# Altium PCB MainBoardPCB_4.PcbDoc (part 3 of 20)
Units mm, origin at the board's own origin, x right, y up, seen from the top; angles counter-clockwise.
Board outline 333.63 x 349.38 mm, 16 copper layers (L1, L2 (GND), L3 (Sign), L4 (GND), L5 (Sign), L6 (PWR/GND), L7(PWR/GND), L8 (Plane_GND), L9 (PWR/GND), L10 (PWR/GND), L11 (PWR/GND), L12 (Sign), L13 (GND), L14 (Sign), L15 (GND), L16), stack 2.502 mm thick; 2205 components, 1648 nets, 8314 pads, 3172 vias.
Unrouted connection lines stored in the file: 5141.
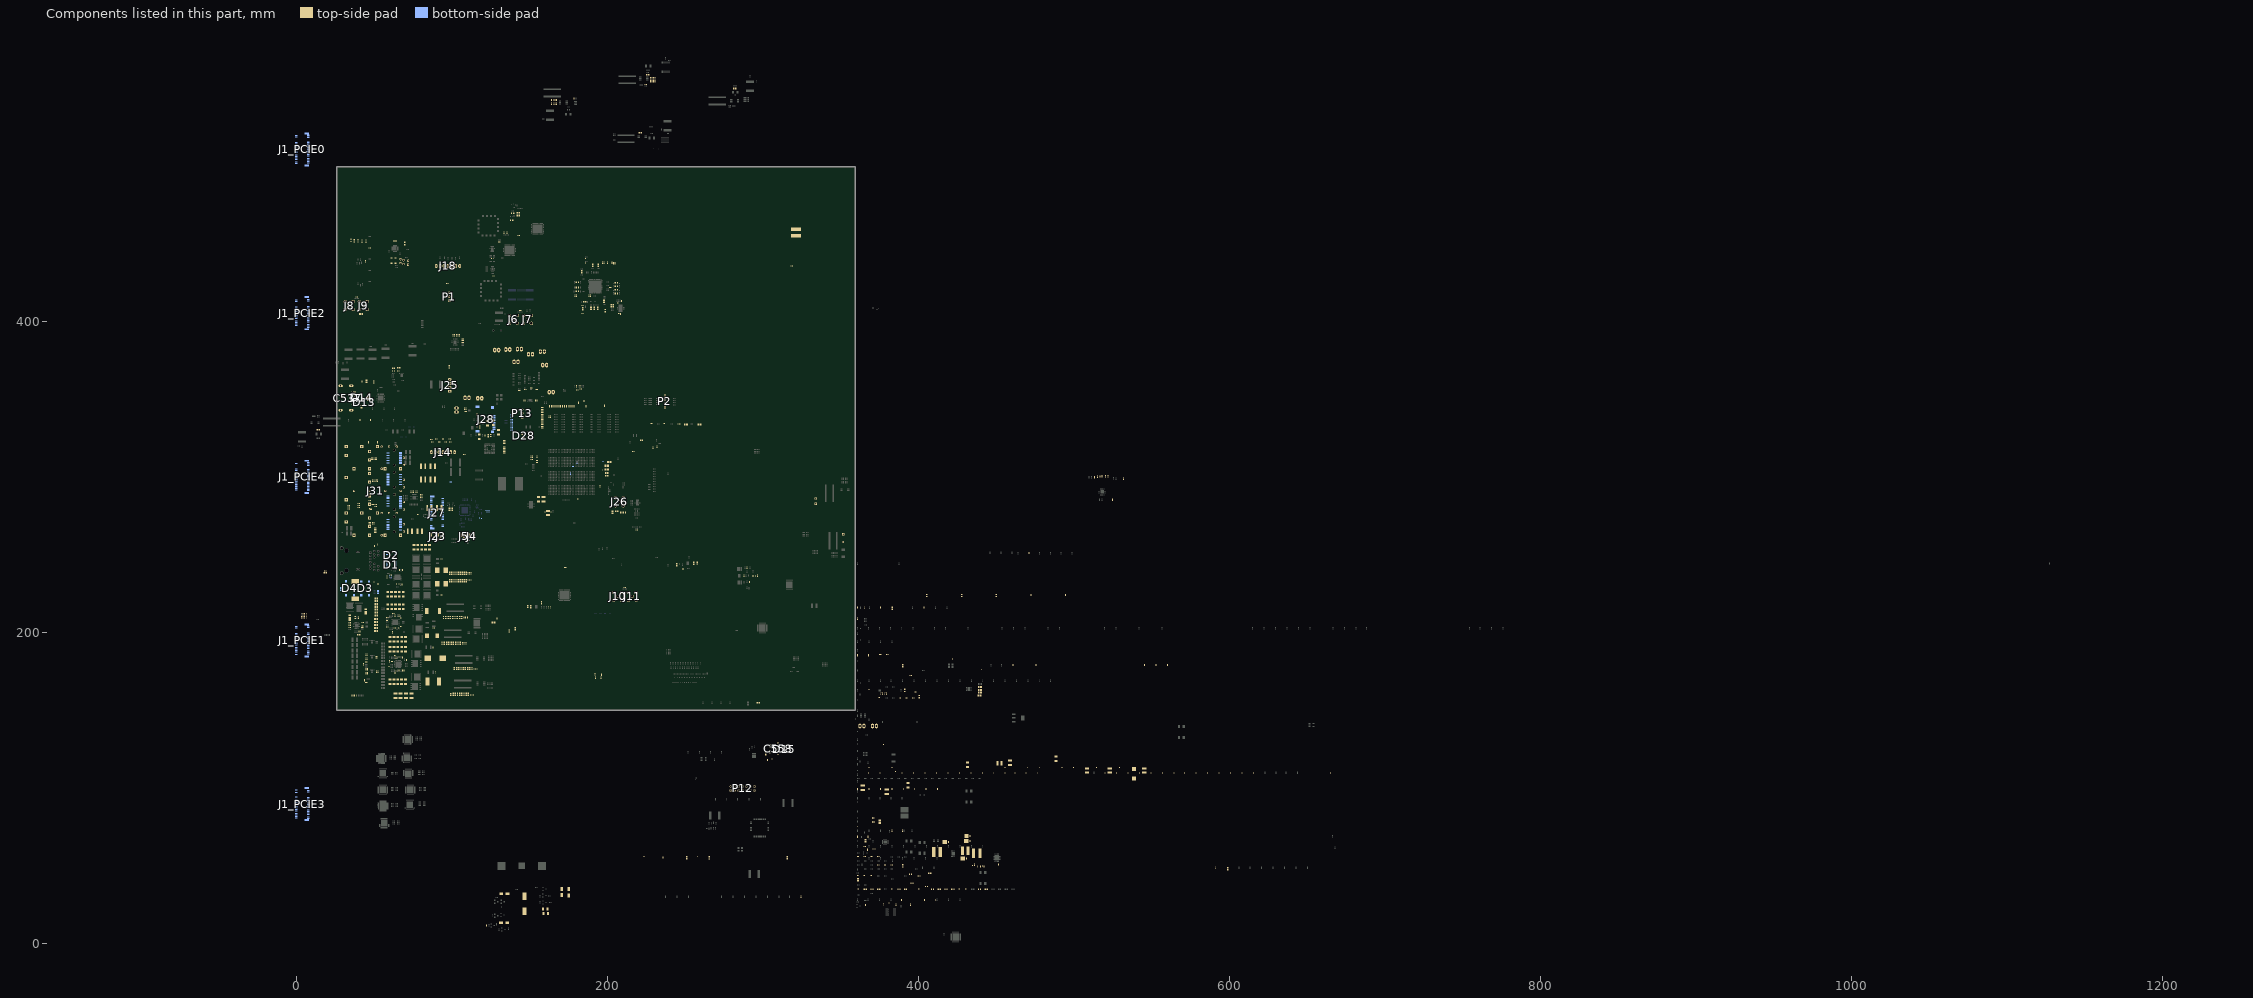
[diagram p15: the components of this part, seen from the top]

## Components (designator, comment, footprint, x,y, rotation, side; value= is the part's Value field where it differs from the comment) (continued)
C333 "10nF" "CAP 0201/0603 RF" 125.971,429.449 r270 top
C334 "100nF" "CAP 0402/1005 RF" 133.51,457.002 r270 top
C335 "100nF" "CAP 0402/1005 RF" 135.6,457.002 r270 top
C336 "100nF" "CAP 0402/1005 RF" 209.427,277.13 r90 top
C337 "100nF" "CAP 0402/1005 RF" 210.486,277.13 r90 top
C338 "100nF" "CAP 0402/1005 RF" 211.544,277.13 r90 top
C339 "10uF" "CAP 0805/2012 RF" 203.289,277.201 r90 top
C340 "1uF" "CAP 0402/1005 RF" 208.369,277.13 r90 top
C341 "100nF" "CAP 0402/1005 RF" 213.821,283.997 r0 top
C342 "100nF" "CAP 0402/1005 RF" 126.635,439.984 r90 top
C343 "100nF" "CAP 0402/1005 RF" 125.635,439.984 r90 top
C344 "10nF" "CAP 0201/0603 RF" 127.056,429.449 r270 top
C345 "22pF" "CAP 0402/1005 RF" 66.32,240.08 r270 top
C346 "100nF" "CAP 0402/1005 RF" 68.336,240.08 r90 top
C347 "10uF" "CAP 1206/3216" 78.111,254.825 r270 top
C348 "10uF" "CAP 1206/3216" 75.629,254.825 r270 top
C349 "22pF" "CAP 0402/1005 RF" 66.055,230.697 r90 top
C350 "100nF" "CAP 0402/1005 RF" 68.072,230.712 r270 top
C351 "1uF" "CAP 0402/1005 RF" 60.756,236.764 r0 top
C352 "10uF" "CAP 1206/3216" 62.772,195.58 r90 top
C353 "10uF" "CAP 1206/3216" 60.29,195.58 r90 top
C354 "4.7 µF" "CAP 0603/1608 RF" 439.306,34.836 r0 top
C355 "4.7 µF" "CAP 0603/1608 RF" 443.624,34.836 r0 top
C356 "1uF" "CAP 0402/1005 RF" 60.541,233.839 r0 top
C357 "100nF" "CAP 0402/1005 RF" 64.44,230.697 r90 top
C358 "1uF" "CAP 0603/1608 RF" 58.293,235.623 r270 top
C359 "100nF" "CAP 0402/1005 RF" 112.323,233.238 r270 top
C360 "470nF" "CAP 0402/1005 RF" 112.324,237.989 r90 top
C361 "1uF" "CAP 0402/1005 RF" 110.434,233.237 r270 top
C362 "4.7uF" "CAP 0603/1608 RF" 101.381,237.989 r90 top
C363 "10uF" "CAP 0603/1608 RF" 100.061,237.989 r90 top
C364 "22uF" "CAP 0603/1608 RF" 102.7,237.989 r90 top
C365 "10uF" "CAP 0603/1608 RF" 98.742,233.237 r270 top
C366 "22uF" "CAP 0603/1608 RF" 98.742,237.989 r90 top
C367 "10uF" "CAP 0603/1608 RF" 101.381,233.237 r270 top
C368 "22uF" "CAP 0603/1608 RF" 100.061,233.237 r270 top
C369 "10uF" "CAP 0603/1608 RF" 102.7,233.237 r270 top
C370 "22uF" "CAP 0603/1608 RF" 104.02,237.989 r90 top
C371 "10uF" "CAP 1206/3216 - 0.8MM" 67.736,195.58 r90 top
C372 "10uF" "CAP 1206/3216 - 0.8MM" 80.593,254.825 r270 top
C373 "10uF" "CAP 1206/3216 - 0.8MM" 85.557,254.825 r270 top
C374 "10uF" "CAP 1206/3216 - 0.8MM" 65.254,195.58 r90 top
C375 "10uF" "CAP 1206/3216 - 0.8MM" 83.075,254.825 r270 top
C376 "10uF" "CAP 1206/3216 - 0.8MM" 70.218,195.58 r90 top
C377 "100nF" "CAP 0402/1005 RF" 111.364,233.238 r270 top
C378 "470nF" "CAP 0402/1005 RF" 110.435,237.989 r90 top
C379 "1uF" "CAP 0402/1005 RF" 111.365,237.989 r90 top
C380 "4.7uF" "CAP 0603/1608 RF" 105.339,237.989 r90 top
C381 "10uF" "CAP 0603/1608 RF" 105.339,233.237 r270 top
C382 "22uF" "CAP 0603/1608 RF" 106.659,233.237 r270 top
C383 "10uF" "CAP 0603/1608 RF" 109.298,237.989 r90 top
C384 "22uF" "CAP 0603/1608 RF" 107.978,233.238 r270 top
C385 "10uF" "CAP 0603/1608 RF" 104.02,233.237 r270 top
C386 "22uF" "CAP 0603/1608 RF" 106.659,237.989 r90 top
C387 "10uF" "CAP 0603/1608 RF" 109.297,233.238 r270 top
C388 "22uF" "CAP 0603/1608 RF" 107.978,237.989 r90 top
C389 "22pF" "CAP 0402/1005 RF" 68.211,183.823 r270 top
C390 "100nF" "CAP 0402/1005 RF" 70.891,182.214 r90 top
C391 "10uF" "CAP 1206/3216" 61.258,224.638 r270 top
C392 "10uF" "CAP 1206/3216" 58.776,224.638 r90 top
C393 "22pF" "CAP 0402/1005 RF" 68.185,175.427 r90 top
C394 "100nF" "CAP 0402/1005 RF" 69.151,175.427 r270 top
C395 "1uF" "CAP 0402/1005 RF" 59.93,181.401 r270 top
C396 "10uF" "CAP 1206/3216" 61.334,216.433 r270 top
C397 "10uF" "CAP 1206/3216" 58.852,216.433 r90 top
C398 "1uF" "CAP 0402/1005 RF" 61.458,181.317 r0 top
C399 "100nF" "CAP 0402/1005 RF" 59.524,178.467 r90 top
C400 "10uF" "CAP 1206/3216 - 0.8MM" 68.78,216.433 r270 top
C401 "10uF" "CAP 1206/3216 - 0.8MM" 66.298,216.433 r270 top
C402 "10uF" "CAP 1206/3216 - 0.8MM" 63.816,216.433 r270 top
C403 "10uF" "CAP 1206/3216 - 0.8MM" 68.704,224.607 r90 top
C404 "10uF" "CAP 1206/3216 - 0.8MM" 66.222,224.637 r90 top
C405 "10uF" "CAP 1206/3216 - 0.8MM" 63.74,224.637 r90 top
C406 "100nF" "CAP 0402/1005 RF" 116.15,176.851 r90 top
C407 "470nF" "CAP 0402/1005 RF" 115.176,176.847 r90 top
C408 "1uF" "CAP 0402/1005 RF" 114.205,176.851 r90 top
C409 "4.7uF" "CAP 0603/1608 RF" 110.122,176.847 r90 top
C410 "10uF" "CAP 0603/1608 RF" 108.699,176.847 r90 top
C411 "22uF" "CAP 0603/1608 RF" 112.941,176.847 r90 top
C412 "10uF" "CAP 0603/1608 RF" 111.544,176.847 r90 top
C413 "22uF" "CAP 0603/1608 RF" 107.302,176.847 r90 top
C414 "10uF" "CAP 0603/1608 RF" 103.061,176.847 r90 top
C415 "22uF" "CAP 0603/1608 RF" 101.638,176.847 r90 top
C416 "10uF" "CAP 0603/1608 RF" 105.905,176.847 r90 top
C417 "22uF" "CAP 0603/1608 RF" 104.47,176.851 r90 top
C418 "100nF" "CAP 0402/1005 RF" 113.877,160.146 r90 top
C419 "470nF" "CAP 0402/1005 RF" 112.903,160.146 r90 top
C420 "1uF" "CAP 0402/1005 RF" 111.932,160.146 r90 top
C421 "4.7uF" "CAP 0603/1608 RF" 107.849,160.146 r90 top
C422 "10uF" "CAP 0603/1608 RF" 106.426,160.146 r90 top
C423 "22uF" "CAP 0603/1608 RF" 110.668,160.146 r90 top
C424 "10uF" "CAP 0603/1608 RF" 109.271,160.146 r90 top
C425 "22uF" "CAP 0603/1608 RF" 105.029,160.147 r90 top
C426 "10uF" "CAP 0603/1608 RF" 100.787,160.147 r90 top
C427 "22uF" "CAP 0603/1608 RF" 99.37,160.137 r90 top
C428 "10uF" "CAP 0603/1608 RF" 103.632,160.147 r90 top
C429 "22uF" "CAP 0603/1608 RF" 102.197,160.147 r90 top
C430 "22pF" "CAP 0402/1005 RF" 65.978,210.639 r270 top
C431 "100nF" "CAP 0402/1005 RF" 67.391,209.114 r0 top
C432 "10uF" "CAP 1206/3216" 62.758,168.173 r270 top
C433 "10uF" "CAP 1206/3216" 60.276,168.173 r90 top
C434 "22pF" "CAP 0402/1005 RF" 65.578,202.374 r90 top
C435 "100nF" "CAP 0402/1005 RF" 67.406,203.864 r0 top
C436 "1uF" "CAP 0402/1005 RF" 58.356,207.523 r0 top
C437 "10uF" "CAP 1206/3216" 62.772,189.281 r270 top
C438 "10uF" "CAP 1206/3216" 60.29,189.281 r90 top
C439 "1uF" "CAP 0402/1005 RF" 58.455,209.529 r0 top
C440 "100nF" "CAP 0402/1005 RF" 58.449,203.522 r0 top
C441 "10uF" "CAP 1206/3216 - 0.8MM" 70.218,189.281 r270 top
C442 "10uF" "CAP 1206/3216 - 0.8MM" 67.736,189.281 r270 top
C443 "10uF" "CAP 1206/3216 - 0.8MM" 65.254,189.281 r270 top
C444 "10uF" "CAP 1206/3216 - 0.8MM" 70.204,168.173 r90 top
C445 "10uF" "CAP 1206/3216 - 0.8MM" 67.722,168.173 r90 top
C446 "10uF" "CAP 1206/3216 - 0.8MM" 65.24,168.173 r90 top
C447 "100nF" "CAP 0402/1005 RF" 109.987,209.5 r90 top
C448 "470nF" "CAP 0402/1005 RF" 108.87,209.5 r90 top
C449 "1uF" "CAP 0402/1005 RF" 107.777,209.5 r90 top
C450 "4.7uF" "CAP 0603/1608 RF" 106.482,209.5 r90 top
C451 "10uF" "CAP 0603/1608 RF" 104.983,209.5 r90 top
C452 "22uF" "CAP 0603/1608 RF" 103.51,209.499 r90 top
C453 "10uF" "CAP 0603/1608 RF" 102.037,209.499 r90 top
C454 "22uF" "CAP 0603/1608 RF" 100.564,209.499 r90 top
C455 "10uF" "CAP 0603/1608 RF" 99.091,209.499 r90 top
C456 "22uF" "CAP 0603/1608 RF" 97.617,209.499 r90 top
C457 "10uF" "CAP 0603/1608 RF" 96.144,209.498 r90 top
C458 "22uF" "CAP 0603/1608 RF" 94.671,209.498 r90 top
C459 "100nF" "CAP 0402/1005 RF" 108.979,192.987 r90 top
C460 "470nF" "CAP 0402/1005 RF" 107.861,192.987 r90 top
C461 "1uF" "CAP 0402/1005 RF" 106.769,192.987 r90 top
C462 "4.7uF" "CAP 0603/1608 RF" 105.474,192.987 r90 top
C463 "10uF" "CAP 0603/1608 RF" 103.975,192.986 r90 top
C464 "22uF" "CAP 0603/1608 RF" 102.502,192.971 r90 top
C465 "10uF" "CAP 0603/1608 RF" 101.028,192.986 r90 top
C466 "22uF" "CAP 0603/1608 RF" 99.555,192.986 r90 top
C467 "10uF" "CAP 0603/1608 RF" 98.082,192.986 r90 top
C468 "22uF" "CAP 0603/1608 RF" 96.609,192.986 r90 top
C469 "10uF" "CAP 0603/1608 RF" 95.136,192.986 r90 top
C470 "22uF" "CAP 0603/1608 RF" 93.662,192.986 r90 top
C471 "100nF" "CAP 0402/1005 RF" 52.457,231.085 r90 top
C472 "100nF" "CAP 0402/1005 RF" 50.082,231.991 r90 top
C473 "100nF" "CAP 0402/1005 RF" 52.387,256.453 r270 top
C474 "100nF" "CAP 0402/1005 RF" 50.178,255.53 r270 top
C479 "100nF" "CAP 0402/1005 RF" 124.389,277.877 r90 bottom
C480 "27pF" "CAP 0402/1005 RF" 117.665,273.146 r90 bottom
C481 "27pF" "CAP 0402/1005 RF" 119.05,273.654 r90 bottom
C482 "100nF" "CAP 0402/1005 RF" 123.424,277.852 r90 bottom
C483 "100nF" "CAP 0402/1005 RF" 122.509,277.903 r90 bottom
C484 "100nF" "CAP 0402/1005 RF" 121.468,277.941 r90 bottom
C485 "1uF" "CAP 0402/1005 RF" 520.141,109.982 r90 top
C486 "1uF" "CAP 0402/1005 RF" 527.507,109.982 r90 top
C487 "100nF" "CAP 0402/1005 RF" 534.873,109.982 r90 top
C488 "100nF" "CAP 0402/1005 RF" 542.252,109.982 r90 top
C489 "10uF" "CAP 0402/1005 RF" 549.618,109.982 r90 top
C490 "10nF" "CAP 0402/1005 RF" 556.984,109.982 r90 top
C491 "1uF" "CAP 0402/1005 RF" 564.35,109.982 r90 top
C492 "1uF" "CAP 0402/1005 RF" 571.208,109.982 r90 top
C493 "1uF" "CAP 0402/1005 RF" 578.587,109.982 r90 top
C494 "100nF" "CAP 0402/1005 RF" 585.953,109.982 r90 top
C495 "100nF" "CAP 0402/1005 RF" 593.319,109.982 r90 top
C496 "100nF" "CAP 0402/1005 RF" 600.685,109.982 r90 top
C497 "10uF" "CAP 0402/1005 RF" 608.051,109.982 r90 top
C498 "10nF" "CAP 0402/1005 RF" 615.429,109.982 r90 top
C499 "1uF" "CAP 0402/1005 RF" 367.944,109.982 r90 top
C500 "1uF" "CAP 0402/1005 RF" 375.31,109.982 r90 top
C501 "100nF" "CAP 0402/1005 RF" 385.255,110.105 r90 top
C502 "100nF" "CAP 0402/1005 RF" 389.547,109.982 r90 top
C503 "10uF" "CAP 0402/1005 RF" 396.913,109.982 r90 top
C504 "10nF" "CAP 0402/1005 RF" 404.279,109.982 r90 top
C505 "1uF" "CAP 0402/1005 RF" 411.645,109.982 r90 top
C506 "1uF" "CAP 0402/1005 RF" 419.011,109.982 r90 top
C507 "1uF" "CAP 0402/1005 RF" 426.39,109.982 r90 top
C508 "1uF" "CAP 0402/1005 RF" 433.756,109.982 r90 top
C509 "100nF" "CAP 0402/1005 RF" 441.122,109.982 r90 top
C510 "100nF" "CAP 0402/1005 RF" 448.488,109.982 r90 top
C511 "100nF" "CAP 0402/1005 RF" 455.6,109.982 r90 top
C512 "100nF" "CAP 0402/1005 RF" 462.216,109.982 r90 top
C513 "10uF" "CAP 0402/1005 RF" 469.328,109.982 r90 top
C514 "10nF" "CAP 0402/1005 RF" 476.44,109.982 r90 top
C515 "4.7uF" "CAP 0603/1608 RF" 136.804,200.812 r90 top
C516 "4.7uF" "CAP 0603/1608 RF" 140.83,202.298 r90 top
C517 "100nF" "CAP 0402/1005 RF" 118.173,334.607 r90 top
C518 "2.2uF" "CAP 1206/3216 - 0.8MM" 126.632,334.937 r90 top
C519 "100nF" "CAP 0402/1005 RF" 121.45,326.621 r90 top
C520 "2.2uF" "CAP 1206/3216 - 0.8MM" 117.602,325.734 r90 top
C521 "100nF" "CAP 0402/1005 RF" 382.93,72.453 r90 top
C522 "1uF" "CAP 0402/1005 RF" 389.788,72.453 r90 top
C523 "4.7uF" "CAP 0603/1608 RF" 117.907,332.121 r90 top
C524 "4.7uF" "CAP 0603/1608 RF" 125.057,326.649 r90 top
C525 "10nF" "CAP 0402/1005 RF" 151.355,313.343 r180 top
C526 "10nF" "CAP 0402/1005 RF" 151.355,312.332 r180 top
C527 "10nF" "CAP 0402/1005 RF" 154.793,309.319 r180 top
C528 "10nF" "CAP 0402/1005 RF" 154.793,310.413 r180 top
C529 "10nF" "CAP 0402/1005 RF" 154.775,312.953 r270 top
C530 "10nF" "CAP 0402/1005 RF" 151.355,311.189 r180 top
C531 "100nF" "CAP 0402/1005 RF" 47.206,447.065 r180 top
C532 "100nF" "CAP 0402/1005 RF" 63.97,451.688 r90 top
C533 "100nF" "CAP 0402/1005 RF" 62.87,451.688 r90 top
C534 "100nF" "CAP 0402/1005 RF" 44.47,438.625 r270 top
C535 "22pF" "CAP 0402/1005 RF" 148.213,330.314 r180 top
C536 "22pF" "CAP 0402/1005 RF" 149.933,330.314 r0 top
C537 "WE-Communication Connectors 692121130100" 692121130100 35.291,358.548 r90 bottom
C538 "1uF" "CAP 0402/1005 RF" 42.177,361.364 r90 top
C539 "4.7uF" "CAP 0603/1608 RF" 49.721,361.034 r90 top
C540 "100nF" "CAP 0402/1005 RF" 45.996,351.904 r180 top
C541 "100nF" "CAP 0402/1005 RF" 46.025,351.079 r180 top
C542 "100nF" "CAP 0402/1005 RF" 46.063,350.101 r180 top
C543 "100nF" "CAP 0402/1005 RF" 46.038,348.996 r180 top
C544 "1uF" "CAP 0402/1005 RF" 403.504,215.989 r90 top
C545 "100nF" "CAP 0402/1005 RF" 360.832,215.989 r90 top
C546 "100nF" "CAP 0402/1005 RF" 365.185,215.849 r90 top
C547 "100nF" "CAP 0402/1005 RF" 375.564,215.989 r90 top
C548 "11pF" "CAP 0402/1005 RF" 62.953,210.639 r270 top
C549 "220pF" "CAP 0402/1005 RF" 62.338,212.229 r180 top
C550 "4.7uF" "CAP 0402/1005 RF" 293.721,236.179 r90 top
C551 "10uF" "CAP 0402/1005 RF" 289.911,241.571 r90 top
C552 "4.7uF" "CAP 0402/1005 RF" 295.118,236.306 r90 top
C553 "10uF" "CAP 0402/1005 RF" 291.435,232.418 r90 top
C554 "4.7uF" "CAP 0402/1005 RF" 296.515,236.433 r90 top
C555 "10uF" "CAP 0402/1005 RF" 287.879,236.366 r90 top
C558 "WR-Communication Connectors 614105150721" 614105150721 309.546,125.025 r90 top
C559 "1uF" "CAP 0402/1005 RF" 301.295,125.371 r90 top
C560 "4.7uF" "CAP 0603/1608 RF" 301.93,121.945 r90 top
C561 "100nF" "CAP 0402/1005 RF" 78.331,275.773 r0 top
C562 "100nF" "CAP 0402/1005 RF" 395.088,172.212 r0 top
C563_5V_to_3V3_for_FTDI "4.7uF" "CAP 0603/1608 RF" 405.447,223.749 r90 top (schematic designator C563)
C563_U_5V_to_3V31 "4.7uF" "CAP 0603/1608 RF" 148.838,216.538 r90 top (schematic designator C563)
C563_U_5V_to_3V32 "4.7uF" "CAP 0603/1608 RF" 255.552,244.424 r270 top (schematic designator C563)
C563_U_5V_to_3V33 "4.7uF" "CAP 0603/1608 RF" 62.446,368.071 r0 top (schematic designator C563)
C564_5V_to_3V3_for_FTDI "4.7uF" "CAP 0603/1608 RF" 427.799,223.749 r90 top (schematic designator C564)
C564_U_5V_to_3V31 "4.7uF" "CAP 0603/1608 RF" 150.832,216.448 r90 top (schematic designator C564)
C564_U_5V_to_3V32 "4.7uF" "CAP 0603/1608 RF" 257.937,244.526 r270 top (schematic designator C564)
C564_U_5V_to_3V33 "4.7uF" "CAP 0603/1608 RF" 65.875,370.103 r0 top (schematic designator C564)
C565_5V_to_3V3_for_FTDI "4.7uF" "CAP 0603/1608 RF" 450.139,223.749 r90 top (schematic designator C565)
C565_U_5V_to_3V31 "4.7uF" "CAP 0603/1608 RF" 157.664,219.018 r270 top (schematic designator C565)
C565_U_5V_to_3V32 "4.7uF" "CAP 0603/1608 RF" 244.615,243.489 r270 top (schematic designator C565)
C565_U_5V_to_3V33 "4.7uF" "CAP 0603/1608 RF" 62.423,369.722 r0 top (schematic designator C565)
C566_5V_to_3V3_for_FTDI "100nF" "CAP 0402/1005 RF" 472.313,224.079 r90 top (schematic designator C566)
C566_U_5V_to_3V31 "100nF" "CAP 0402/1005 RF" 163.601,216.148 r90 top (schematic designator C566)
C566_U_5V_to_3V32 "100nF" "CAP 0402/1005 RF" 246.545,243.522 r270 top (schematic designator C566)
C566_U_5V_to_3V33 "100nF" "CAP 0402/1005 RF" 65.568,368.071 r0 top (schematic designator C566)
C567_5V_to_3V3_for_FTDI "2.2uF" "CAP 0402/1005 RF" 494.665,224.079 r90 top (schematic designator C567)
C567_U_5V_to_3V31 "2.2uF" "CAP 0402/1005 RF" 162.312,216.16 r90 top (schematic designator C567)
C567_U_5V_to_3V32 "2.2uF" "CAP 0402/1005 RF" 248.588,240.767 r90 top (schematic designator C567)
C567_U_5V_to_3V33 "2.2uF" "CAP 0402/1005 RF" 68.018,358.927 r0 top (schematic designator C567)
C568 "4.7uF" "CAP 0402/1005 RF" 392.43,157.861 r0 top
C569 "4.7uF" "CAP 0402/1005 RF" 396.748,157.861 r0 top
C570 "4.7uF" "CAP 0402/1005 RF" 388.112,157.861 r0 top
C571 "1nF" "CAP 0201/0603 RF" 374.777,158.115 r0 top
C572 "10uF" "CAP 0603/1608 RF" 202.4,410.04 r270 top
C573 "10nF" "CAP 0201/0603 RF" 207.236,405.087 r180 top
C574 "10uF" "CAP 0805/2012 RF" 126.822,206.235 r0 top
C575 "10uF" "CAP 0805/2012 RF" 41.641,404.621 r0 top
C576 "10uF" "CAP 0603/1608 RF" 203.797,410.071 r270 top
C577 "10nF" "CAP 0201/0603 RF" 206.789,411.818 r180 top
C578 "100nF" "CAP 0402/1005 RF" 208.996,413.088 r270 top
C579 "100nF" "CAP 0402/1005 RF" 208.496,404.697 r90 top
C580 "4.7uF" "CAP 0805/2012 RF" 439.547,161.275 r0 top
C581 "10uF" "CAP 0805/2012 RF" 439.547,163.068 r0 top
C582 "4.7uF" "CAP 0805/2012 RF" 439.547,164.846 r0 top
C583 "100nF" "CAP 0402/1005 RF" 398.154,161.671 r0 top
C584 "4.7uF" "CAP 0805/2012 RF" 439.293,159.385 r0 top
C585 "100nF" "CAP 0402/1005 RF" 368.198,162.865 r90 top
C586 "2.2uF" "CAP 1206/3216 - 0.8MM" 122.999,334.34 r90 top
C587 "2.2uF" "CAP 1206/3216 - 0.8MM" 130.035,328.79 r90 top
C588 "100nF" "CAP 0402/1005 RF" 185.89,439.977 r270 top
C589 "100nF" "CAP 0402/1005 RF" 185.89,437.114 r270 top
C590 "100nF" "CAP 0402/1005 RF" 184.121,410.218 r0 top
C591 "10uF" "CAP 0402/1005 RF" 184.121,406.154 r0 top
C592 "100nF" "CAP 0402/1005 RF" 184.121,405.069 r0 top
C593 "100nF" "CAP 0402/1005 RF" 188.176,416.431 r90 top
C594 "100nF" "CAP 0402/1005 RF" 189.1,416.431 r90 top
C595 "10uF" "CAP 0805/2012 RF" 28.639,227.851 r90 bottom
C596 "10uF" "CAP 0805/2012 RF" 52.54,225.895 r90 bottom
C597 "1uF" "CAP 0402/1005 RF" 34.332,206.35 r0 top
C598 "10uF" "CAP 0603/1608 RF" 37.846,209.537 r270 top
C603 "43pF" "CAP 0201/0603 RF" 430.339,35.014 r0 top
C604 "1µF" "CAP 0402/1005 RF" 426.022,35.014 r0 top
C605 "100pF" "CAP 0201/0603 RF" 400.126,35.014 r0 top
C606 "4.7 µF" "CAP 0603/1608 RF" 405.267,36.589 r0 top
C607 "4.7 µF" "CAP 0603/1608 RF" 409.092,34.836 r0 top
C609 "FC0H224ZFTBR24" FC0H224ZFTBR24 146.837,25.502 r270 top
C610 "4.7 µF" "CAP 0603/1608 RF" 413.41,34.836 r0 top
C611 "4.7 µF" "CAP 0603/1608 RF" 417.728,34.836 r0 top
C612 "43pF" "CAP 0201/0603 RF" 382.854,35.014 r0 top
C613 "4.7 µF" "CAP 0603/1608 RF" 387.502,34.836 r0 top
C614 "4.7 µF" "CAP 0603/1608 RF" 391.82,34.836 r0 top
C615 "4.7 µF" "CAP 0603/1608 RF" 395.938,38.697 r0 top
C616 "100pF" "CAP 0201/0603 RF" 361.251,35.014 r0 top
C617 "4.7 µF" "CAP 0603/1608 RF" 365.9,34.836 r0 top
C618 "4.7 µF" "CAP 0603/1608 RF" 370.218,34.836 r0 top
C619 "4.7 µF" "CAP 0603/1608 RF" 374.536,34.836 r0 top
C620 "4.7 µF" "CAP 0603/1608 RF" 394.945,44.374 r0 top
C621 "4.7 µF" "CAP 0603/1608 RF" 400.494,43.307 r0 top
C622 "4.7 µF" "CAP 0603/1608 RF" 407.276,45.174 r0 top
C623 "100nF" "CAP 0402/1005 RF" 387.198,43.485 r0 top
C624 "10nF" "CAP 0201/0603 RF" 360.934,43.637 r0 top
C625 "10nF" "CAP 0201/0603 RF" 365.252,43.637 r0 top
C626 "10nF" "CAP 0201/0603 RF" 369.57,43.637 r0 top
C627 "100nF" "CAP 0201/0603 RF" 197.272,309.647 r90 bottom
C628 "470nF" "CAP 0402/1005 RF" 180.397,309.042 r90 bottom
C629 "100nF" "CAP 0201/0603 RF" 197.104,304.165 r90 top
C630 "470nF" "CAP 0402/1005 RF" 176.39,302.031 r90 bottom
C631 "10uF" "CAP 0603/1608 RF" 199.567,300.723 r180 top
C632 "470nF" "CAP 0402/1005 RF" 177.902,306.54 r0 bottom
C633 "3nF" "CAP 0402/1005 RF" 93.442,247.284 r180 top
C634 "330pF" "CAP 0402/1005 RF" 61.028,236.114 r270 bottom
C635 "6.8nF" "CAP 0402/1005 RF" 60.062,236.114 r270 bottom
C636 "3nF" "CAP 0402/1005 RF" 93.332,224.031 r180 top
C637 "1.2nF" "CAP 0402/1005 RF" 87.909,190.2 r270 top
C638 "1.2nF" "CAP 0402/1005 RF" 89.332,174.38 r270 top
C639 "47nF" "CAP 0402/1005 RF" 66.141,183.759 r270 top
C640 "47nF" "CAP 0402/1005 RF" 66.161,175.503 r90 top
C641 "470pF" "CAP 0402/1005 RF" 64.175,175.557 r90 top
C642 "56pF" "CAP 0402/1005 RF" 64.175,183.66 r270 top
C643 "8.2nF" "CAP 0402/1005 RF" 63.51,173.949 r180 top
C644 "820pF" "CAP 0402/1005 RF" 63.565,185.176 r180 top
C645 "1.2nF" "CAP 0402/1005 RF" 88.354,202.857 r180 top
C646 "1.2nF" "CAP 0402/1005 RF" 84.112,207.488 r0 top
C647 "47nF" "CAP 0402/1005 RF" 63.953,210.654 r270 top
C648 "47nF" "CAP 0402/1005 RF" 63.741,202.373 r90 top
C649 "100nF" "CAP 0402/1005 RF" 410.883,27.889 r90 top
C650 "180pF" "CAP 0402/1005 RF" 62.828,202.374 r90 top
C651 "100nF" "CAP 0402/1005 RF" 404.025,27.889 r90 top
C652 "2.2nF" "CAP 0402/1005 RF" 61.925,200.059 r90 top
C653 "100nF" "CAP 0402/1005 RF" 395.059,24.816 r90 top
C654 "100nF" "CAP 0402/1005 RF" 374.205,55.74 r0 top
C655 "5.6nF" "CAP 0402/1005 RF" 369.887,55.74 r0 top
C656 "5.6nF" "CAP 0402/1005 RF" 365.57,55.74 r0 top
C657 "5.6nF" "CAP 0402/1005 RF" 361.251,55.74 r0 top
C658 "100nF" "CAP 0402/1005 RF" 324.574,29.985 r90 top
C659 "4.7uF" "CAP 0603/1608 RF" 315.62,55.118 r90 top
C660 "100nF" "CAP 0402/1005 RF" 591.261,48.603 r90 top
C661 "4.7uF" "CAP 0603/1608 RF" 251.142,55.118 r90 top
C662 "100nF" "CAP 0402/1005 RF" 257.823,55.448 r90 top
C663 "27pF" "CAP 0402/1005 RF" 235.852,55.258 r90 top
C664 "27pF" "CAP 0402/1005 RF" 223.609,55.448 r90 top
C665 "100nF" "CAP 0402/1005 RF" 305.854,118.135 r90 top
C666 "100nF" "CAP 0402/1005 RF" 434.81,50.47 r90 top
C667 "100nF" "CAP 0402/1005 RF" 436.08,50.568 r90 top
C668 "100nF" "CAP 0402/1005 RF" 438.175,49.441 r90 top
C669 "100nF" "CAP 0402/1005 RF" 439.839,49.39 r90 top
C670 "100nF" "CAP 0402/1005 RF" 441.164,49.336 r90 top
C671 "100nF" "CAP 0402/1005 RF" 442.239,49.39 r90 top
C673 "100nF" "CAP 0402/1005 RF" 302.959,117.983 r90 top
C674 "4.7uF" "CAP 0402/1005 RF" 378.549,50.521 r0 top
C675 "4.7uF" "CAP 0402/1005 RF" 382.867,50.521 r0 top
C676 "4.7uF" "CAP 0402/1005 RF" 374.231,50.521 r0 top
C677 "100nF" "CAP 0402/1005 RF" 389.293,27.889 r90 top
C678 "100uF" "CAP 1206/3216" 160.249,19.164 r0 top
C679 "100uF" "CAP 1206/3216" 160.172,22.123 r0 top
C680 "1uF" "CAP 0402/1005 RF" 122.364,11.557 r90 top
C693 "470nF" "CAP 0402/1005 RF" 39.98,209.427 r90 top
C694 "4.7uF" "CAP 0603/1608 RF" 18.637,238.218 r0 top
C695 "10uF" "CAP 0805/2012 RF" 51.294,206.694 r180 top
C696 "10uF" "CAP 0805/2012 RF" 51.294,202.914 r180 top
C697 "10uF" "CAP 0805/2012 RF" 51.294,204.804 r180 top
C698 "10uF" "CAP 0805/2012 RF" 51.294,208.585 r180 top
C699 "10uF" "CAP 0805/2012 RF" 51.294,201.023 r180 top
C700 "1uF" "CAP 0402/1005 RF" 18.637,239.357 r0 top
C701 "12nF" "CAP 0402/1005 RF" 41.097,200.511 r90 top
C702 "36pF" "CAP 0402/1005 RF" 40.17,200.511 r90 top
C703 "15nF" "CAP 0402/1005 RF" 42.517,204.097 r180 top
C704 "1uF" "CAP 0603/1608 RF" 40.157,198.45 r180 top
C705 "10uF" "CAP 0603/1608 RF" 222.045,323.494 r0 top
C706 "10nF" "CAP 0201/0603 RF" 180.892,285.703 r0 top
C707 "10uF" "CAP 0805/2012 RF" 259.183,333.794 r0 top
C708 "10uF" "CAP 0805/2012 RF" 250.534,333.794 r0 top
C709 "10uF" "CAP 0603/1608 RF" 245.988,333.997 r0 top
C710 "10nF" "CAP 0201/0603 RF" 236.679,334.327 r0 top
C711 "100nF" "CAP 0402/1005 RF" 216.682,316.433 r0 top
C712 "100nF" "CAP 0402/1005 RF" 228.36,334.175 r0 top
C713 "100nF" "CAP 0402/1005 RF" 365.57,62.319 r0 top
C714 "330nF" "CAP 0603/1608 RF" 371.479,60.719 r0 top
C715 "100nF" "CAP 0402/1005 RF" 385.712,24.794 r90 top
C716 "100nF" "CAP 0402/1005 RF" 381.013,25.552 r90 top
C717 "100nF" "CAP 0402/1005 RF" 377.762,25.155 r90 top
C718 "100nF" "CAP 0402/1005 RF" 366.065,24.667 r90 top
C719 "1nF" "CAP 0201/0603 RF" 360.68,75.425 r90 top
C720 "1uF" "CAP 0402/1005 RF" 146.52,349.06 r90 top
C721 "1uF" "CAP 0402/1005 RF" 147.511,349.06 r90 top
C722 "1uF" "CAP 0402/1005 RF" 153.683,349.142 r90 top
C723 "1uF" "CAP 0402/1005 RF" 154.673,349.142 r90 top
C724 "10nF" "CAP 0201/0603 RF" 388.645,29.985 r90 top
C725 "10nF" "CAP 0201/0603 RF" 381.279,29.985 r90 top
C726 "10nF" "CAP 0201/0603 RF" 373.901,29.985 r90 top
C727 "10nF" "CAP 0201/0603 RF" 366.535,29.985 r90 top
C728 "100nF" "CAP 0402/1005 RF" 545.478,179.032 r90 top
C729 "100nF" "CAP 0402/1005 RF" 552.844,179.032 r90 top
C730 "100nF" "CAP 0402/1005 RF" 560.21,179.032 r90 top
C731 "2.2uF" "CAP 0402/1005 RF" 40.97,336.575 r90 top
C732 "100nF" "CAP 0402/1005 RF" 47.828,336.575 r90 top
C733 "1uF" "CAP 0402/1005 RF" 129.003,208.851 r90 top
C734 "1uF" "CAP 0402/1005 RF" 475.615,179.032 r90 top
C735 "100nF" "CAP 0402/1005 RF" 460.87,179.032 r90 top
C736 "9pF" "CAP 0201/0603 RF" 421.932,183.172 r90 top
C737 "9pF" "CAP 0201/0603 RF" 440.741,176.352 r90 top
C738 "6TPE680MI" "CAP POL 2917/7343" 538.734,109.042 r90 top
C739 "100uF" "CAP 1210/3225 - 1MM" 545.224,111.176 r90 top
C740 "4.7uF" "CAP 0402/1005 RF" 377.609,128.283 r90 top
C741 "4.7uF" "CAP 0402/1005 RF" 159.918,277.794 r90 top
C742 "100uF" "CAP 1210/3225 - 1MM" 523.113,111.176 r90 top
C743 "4.7uF" "CAP 0402/1005 RF" 529.311,112.674 r90 top
C744 "47uF" "CAP 1206/3216 - 0.8MM" 488.455,118.732 r90 top
C745 "4.7uF" "CAP 0402/1005 RF" 492.455,112.674 r90 top
C746 "4.7uF" "CAP 0402/1005 RF" 499.821,112.674 r90 top
C747 "100uF" "CAP 1210/3225 - 1MM" 508.368,111.176 r90 top
C748 "4.7uF" "CAP 0402/1005 RF" 514.566,112.674 r90 top
C749 "47uF" "CAP 1206/3216 - 0.8MM" 155.753,285.612 r270 top
C750 "4.7uF" "CAP 0402/1005 RF" 231.951,319.325 r90 top
C751 "100uF" "CAP 1210/3225 - 1MM" 452.183,115.875 r0 top
C752 "4.7uF" "CAP 0402/1005 RF" 455.612,112.674 r90 top
C753 "100uF" "CAP 1210/3225 - 1MM" 458.902,116.116 r90 top
C754 "4.7uF" "CAP 0402/1005 RF" 470.357,112.674 r90 top
C755 "4.7uF" "CAP 0402/1005 RF" 477.723,112.674 r90 top
C756 "47uF" "CAP 1206/3216 - 0.8MM" 431.546,114.821 r90 top
C757 "100uF" "CAP 1210/3225 - 1MM" 158.966,285.56 r90 top
C758 "4.7uF" "CAP 0402/1005 RF" 229.361,318.746 r90 top
C759 "47uF" "CAP 1206/3216 - 0.8MM" 393.268,101.803 r90 top
C760 "100uF" "CAP 1210/3225 - 1MM" 161.874,276.784 r270 top
C761 "4.7uF" "CAP 0402/1005 RF" 163.792,277.794 r90 top
C762 "100uF" "CAP 1210/3225 - 1MM" 364.236,99.971 r90 top
C763 "4.7uF" "CAP 0402/1005 RF" 368.211,112.674 r90 top
C764 "100uF" "CAP 1210/3225 - 1MM" 379.705,97.399 r90 top
C765 "4.7uF" "CAP 0402/1005 RF" 382.943,112.674 r90 top
C766 "22uF" "CAP 1210/3225 - 1MM" 73.992,159.249 r270 top
C767 "22uF" "CAP 1210/3225 - 1MM" 70.524,159.25 r270 top
C768 "22uF" "CAP 1210/3225 - 1MM" 67.084,159.249 r270 top
C769 "22uF" "CAP 1210/3225 - 1MM" 63.68,159.249 r270 top
C770 "100nF" "CAP 0402/1005 RF" 38.538,159.341 r270 top
C771 "100nF" "CAP 0402/1005 RF" 37.531,159.341 r270 top
C772 "100nF" "CAP 0402/1005 RF" 36.624,159.341 r270 top
C773 "100nF" "CAP 0402/1005 RF" 35.693,159.341 r270 top
C774 "10uF" "CAP 0805/2012 RF" 51.366,221.852 r0 top
C775 "10uF" "CAP 0805/2012 RF" 51.366,220.038 r0 top
C776 "10uF" "CAP 0805/2012 RF" 51.366,218.215 r0 top
C777 "10uF" "CAP 0805/2012 RF" 51.366,216.47 r0 top
C778 "4.7uF" "CAP 0805/2012 RF" 51.366,214.657 r0 top
C779 "4.7uF" "CAP 0805/2012 RF" 51.366,212.847 r0 top
C780 "4.7uF" "CAP 0805/2012 RF" 51.366,210.952 r0 top
C781 "4.7uF" "CAP 0805/2012 RF" 361.201,40.919 r90 top
C782 "4.7uF" "CAP 0402/1005 RF" 405.041,99.314 r90 top
C783 "100nF" "CAP 0402/1005 RF" 412.407,99.314 r90 top
C784 "4.7uF" "CAP 0402/1005 RF" 390.309,99.314 r90 top
C785 "100nF" "CAP 0402/1005 RF" 397.675,99.314 r90 top
C786 "4.7uF" "CAP 0402/1005 RF" 375.564,99.314 r90 top
C787 "100nF" "CAP 0402/1005 RF" 382.93,99.314 r90 top
C788 "4.7uF" "CAP 0402/1005 RF" 360.832,99.314 r90 top
C789 "100nF" "CAP 0402/1005 RF" 368.198,99.314 r90 top
C790 "100nF" "CAP 0402/1005 RF" 664.972,109.982 r90 top
C791 "100nF" "CAP 0402/1005 RF" 471.068,251.092 r90 top
C792 "100nF" "CAP 0402/1005 RF" 451.536,50.66 r90 top
D1 "SLVU2.8-4BTG TVS Array" SLVU2.8-4 61.176,243.357 r0 bottom
D2 "SLVU2.8-4BTG TVS Array" SLVU2.8-4 61.189,249.58 r0 bottom
D3 "DF01S2" "DF005S2 - DF10S2" 44.298,228.282 r90 bottom locked
D4 "DF01S2" "DF005S2 - DF10S2" 34.43,228.346 r90 bottom locked
D5 "LTST-C190GKT" "LED 0603/1608 GREEN" 37.231,451.764 r90 top
D6 "LTST-C190GKT" "LED 0603/1608 GREEN" 35.199,452.018 r90 top
D7 "LTST-C190GKT" "LED 0603/1608 GREEN" 39.629,451.764 r90 top
D8 "LTST-C190GKT" "LED 0603/1608 GREEN" 44.724,451.637 r90 top
D9 "LTST-C190GKT" "LED 0603/1608 GREEN" 42.311,451.637 r270 top
D10 "LTST-C190GKT" "LED 0603/1608 GREEN" 69.708,450.037 r270 top
D11 "BAT54T1G" BAT54T1G 63.745,439.095 r90 top
D12 "BAT54T1G" BAT54T1G 61.326,439.095 r90 top
D13 "TPD2EUSB30DRTR" TPD2EUSB30 43.739,347.942 r0 top
D14 "TPD4EUSB30DQAR" TPD4EUSB30 42.137,350.757 r180 top
D15 "TPD2EUSB30DRTR" TPD2EUSB30 313.817,124.828 r0 top
D16 "MBRM140T3" "CASE 457" 432.475,65.773 r0 top
D17 "MBRM140T3" "CASE 457" 432.576,68.961 r0 top
D18 "MBRM140T3" "CASE 457" 418.594,65.316 r0 top
D19 "MBRM140T3" "CASE 457" 430.212,54.508 r0 top
D20 "S1M-13-F" S1M-13-F 133.794,31.991 r180 top
D21 "S1M-13-F" S1M-13-F 133.629,13.259 r180 top
D22 "S1M-13-F" S1M-13-F 170.726,33.033 r270 top
D23 "S1M-13-F" S1M-13-F 175.222,32.88 r270 top
D26 "DFLS1100-7" DFLS1100 34.353,210.071 r270 top
D27 "DFLS1100-7" DFLS1100 44.666,214.084 r270 top
D28 "BAS40-04-TP" BAS40-04-TP 146.24,326.314 r270 top
FB1_PCIE0 "Ferrite Chip" "FER 0603/1608" 98.387,370.651 r90 top (schematic designator FB1)
FB1_PCIE1 "Ferrite Chip" "FER 0603/1608" 225.984,558.682 r180 top (schematic designator FB1)
FB1_PCIE2 "Ferrite Chip" "FER 0603/1608" 14.17,330.298 r0 top (schematic designator FB1)
FB1_PCIE3 "Ferrite Chip" "FER 0603/1608" 281.991,549.732 r180 top (schematic designator FB1)
FB1_PCIE4 "Ferrite Chip" "FER 0603/1608" 221.158,521.208 r180 top (schematic designator FB1)
FB2 "220Ohm" "FER 0603/1608" 98.514,279.109 r90 top
FB3 "220Ohm" "FER 0603/1608" 142.701,468.051 r180 top
FB4 "220Ohm" "FER 0603/1608" 100.292,279.109 r90 top
FB5 "220Ohm" "FER 0603/1608" 139.058,469.448 r180 top
FB6 "220Ohm" "FER 0603/1608" 138.383,465.003 r180 top
FB7 "220Ohm" "FER 0603/1608" 142.701,469.702 r180 top
FB8 "220R" "FER 0603/1608" 185.4,412.473 r0 top
FB9 "220R" "FER 0603/1608" 205.829,424.941 r180 top
FB10 "220R" "FER 0603/1608" 197.837,412.845 r90 top
FB11 "220R" "FER 0603/1608" 180.792,425.16 r0 top
FB12 "220R" "FER 0603/1608" 193.764,408.476 r90 top
FB13 "220R" "FER 0603/1608" 183.477,431.815 r270 top
FB14 "220R" "FER 0603/1608" 189.49,408.476 r90 top
FB15 "220R" "FER 0603/1608" 194.272,436.075 r270 top
FB16 "220R" "FER 0603/1608" 205.829,420.266 r180 top
FB17 "220R" "FER 0603/1608" 190.49,436.075 r270 top
FB18 "220R" "FER 0603/1608" 205.829,422.613 r180 top
FB19 "220R" "FER 0603/1608" 205.829,417.914 r180 top
FB20 "220R" "FER 0603/1608" 180.77,421.766 r0 top
FB21 "220R" "FER 0603/1608" 191.49,408.476 r90 top
FB22 "220R" "FER 0603/1608" 180.77,419.266 r0 top
FB23 "Ferrite Chip" "FER 0603/1608" 297.015,154.838 r0 top
FB24 "Ferrite Chip" "FER 0603/1608" 205.996,277.901 r0 top
FB25 "Ferrite Chip" "FER 0603/1608" 123.533,326.369 r90 top
FB26 "220R" "FER 0603/1608" 45.11,361.44 r90 top
FB27 "220R" "FER 0603/1608" 41.93,345.237 r90 top
FB28 "220R" "FER 0603/1608" 390.042,178.498 r90 top
FB29 "220R" "FER 0603/1608" 383.184,215.456 r90 top
FB31 "220R" "FER 0603/1608" 304.432,123.266 r90 top
FB32 "220R" "FER 0603/1608" 304.775,127.089 r90 top
FB33 "120R" "FER 0603/1608" 400.685,158.75 r90 top
FB34 "330R" "FER 0603/1608" 391.325,162.672 r90 top
FB35 "220Ohm" "FER 0603/1608" 366.022,65.915 r90 top
FB36 "220R" "FER 0603/1608" 198.617,406.919 r270 top
FB37 "220R" "FER 0603/1608" 184.121,408.186 r270 top
FB38 "600R" "FER 0805/2012" 201.358,309.448 r180 top
FB39 "600R" "FER 0805/2012" 199.568,307.149 r180 top
FB40 "600R" "FER 0805/2012" 199.579,304.749 r180 top
FB41 "600R" "FER 0805/2012" 375.12,78.105 r90 top
FB42 "120R" "FER 0603/1608" 199.593,302.489 r180 top
FB43 "220R" "FER 0603/1608" 598.881,48.069 r90 top
FB44 "220R" "FER 0603/1608" 265.443,54.915 r90 top
FB45 "120R" "FER 0603/1608" 389.903,49.784 r90 top
J1_PCIE0 "Key M" "M.2 KEY M" 3.725,510.508 r90 bottom (schematic designator J1)
J1_PCIE1 "Key M" "M.2 KEY M" 3.725,194.813 r90 bottom (schematic designator J1)
J1_PCIE2 "Key M" "M.2 KEY M" 3.725,405.276 r90 bottom (schematic designator J1)
J1_PCIE3 "Key M" "M.2 KEY M" 3.725,89.581 r90 bottom (schematic designator J1)
J1_PCIE4 "Key M" "M.2 KEY M" 3.725,300.045 r90 bottom (schematic designator J1)
J2 "1909763-1" TECO-1909763-1_V 88.279,262.674 r0 top
J3 "1909763-1" TECO-1909763-1_V 92.854,262.674 r0 top
J4 "1909763-1" TECO-1909763-1_V 112.869,262.534 r0 top
J5 "1909763-1" TECO-1909763-1_V 107.815,262.534 r0 top
J6 "5-1814832-1" TECO-5-1814832-1_V 139.56,401.249 r180 bottom
J7 "5-1814832-1" TECO-5-1814832-1_V 148.577,401.249 r180 bottom
J8 "5-1814832-1" TECO-5-1814832-1_V 34.011,410.185 r180 bottom
J9 "5-1814832-1" TECO-5-1814832-1_V 43.028,410.185 r180 bottom
J10 "5-1814832-1" TECO-5-1814832-1_V 206.667,223.152 r180 bottom
J11 "5-1814832-1" TECO-5-1814832-1_V 216.065,223.152 r180 bottom
J12 "I2C_0Master" "MOLEX KK 0022272021" 163.919,354.457 r0 top
J13 "I2C1_Master" "MOLEX KK 0022272021" 103.002,342.925 r270 top
J14 "7 Pin" "JST XH B7B-XH-A" 94.317,315.9 r180 bottom
J15 "GPIO0_12" "MOLEX KK 0022272021" 159.728,371.881 r0 top
J16 "GPIO0_23" "MOLEX KK 0022272021" 141.313,373.913 r0 top
J17 "GPIO1_38" "MOLEX KK 0022272021" 128.867,381.533 r0 top
J18 "7 Pin" "JST XH B7B-XH-A" 97.485,435.597 r0 bottom
J19 "GPIO2_66" "MOLEX KK 0022272021" 135.979,381.914 r0 top
J20 "GPIO2_70" "MOLEX KK 0022272021" 143.472,382.168 r0 top
J21 "GPIO2_72" "MOLEX KK 0022272021" 150.584,378.866 r0 top
J22 "GPIO2_73" "MOLEX KK 0022272021" 158.204,380.517 r0 top
J23 "GPIO2_74" "MOLEX KK 0022272021" 117.945,350.545 r0 top
J24 "GPIO2_75" "MOLEX KK 0022272021" 109.817,350.799 r0 top
J25 "SPI1" "JST XH B4B-XH-A" 98.641,358.8 r90 top
J26 "5-1814832-1" TECO-5-1814832-1_V 207.704,283.997 r90 bottom
J27 "Key M-SATA CHINA" "M.2 KEY M - NVMe" 90.471,277.021 r270 bottom locked
J28 "693071020811" 693071020811 119.487,337.182 r90 bottom locked
J29 "SYSMON_VP_VN" "MOLEX KK 0022272021" 371.78,139.789 r0 top
J30 "DxN_DxP" "MOLEX KK 0022272021" 363.703,139.789 r0 top
J31 "SFP Connector" 2007132 37.104,262.472 r90 bottom
L1 "NRS4018T4R7MDGJV" NRS8040 79.329,264.987 r0 top
L2 "NRS4018T4R7MDGJV" NRS8040 73.055,264.987 r0 top
L3 "NRS4018T4R7MDGJV" NRS8040 91.846,279.997 r0 top
L4 "NRS4018T4R7MDGJV" NRS8040 85.573,279.997 r0 top
L5 "NRS4018T4R7MDGJV" NRS8040 87.768,298.256 r0 top
L6 "NRS4018T4R7MDGJV" NRS8040 81.494,298.256 r0 top
L7 "NRS4018T4R7MDGJV" NRS8040 87.768,306.777 r0 top
L8 "NRS4018T4R7MDGJV" NRS8040 81.494,306.777 r0 top
L9 "MGV0605R22M-10" MGV0605 93.417,240.05 r0 top
L10 "MGV0605R22M-10" MGV0605 93.442,231.202 r0 top
L11 "MGV10041R2M-10" "MGV1004 Series" 89.295,183.236 r0 top
L12 "744373560068" 744373560068 88.108,168.37 r0 top
L13 "CDRH5D28-8R2" CDRH5D28 321.272,457.225 r90 top
L15 "Inductance" "FER 0603/1608" 422.25,34.76 r0 top
L16 "CDRH5D28-4R2" CDRH5D28 437.54,57.899 r0 top
L17 "CDRH5D28-8R2" CDRH5D28 412.001,58.763 r0 top
L18 "CDRH4D28NP-3R3NC" CDRH4D28NP 430.098,59.55 r0 top
L19 "3.3uH, 13.8A" WE-CHSA_1011 87.928,213.721 r0 top
L20 "1.5 uH, 16.5 A" WE-HCC_8070 87.389,197.752 r0 top
L22 "SRP1265A-220M" SRP1265A-220M 37.948,227.19 r90 top locked
P1 "Header 3" HDR1X3 98.4,413.271 r90 top
P2 "Header 4" HDR1X4 237.071,352.323 r270 top
P3 "Header 2" HDR1X2 67.041,437.464 r90 top
P4 "Header 2" HDR1X2 68.946,436.829 r90 top
P5 "Header 2" HDR1X2 71.867,436.448 r90 top
P6 "640456-2" TECO-640456-2_V 377.711,160.528 r0 top
P7 "Plug" PIN1 334.099,282.727 r90 top
P8 "Plug" PIN1 334.099,286.029 r0 top
P9 "Plug" PIN1 351.752,263.042 r90 top
P10 "Plug" PIN1 351.498,258.089 r0 top
P11 "Header 2" HDR1X2 370.942,78.054 r90 top
P12 "Header 7X2" HDR2X7 279.349,98.361 r0 top
P13 "Header 3" HDR1X3 145.275,338.239 r90 top
R1 "0R" "RES 0402/1005 RF" 379.959,185.649 r0 top
R2 "0R" "RES 0402/1005 RF" 375.628,185.649 r0 top
R3_I2C_Bridge "1kR" "RES 0402/1005 RF" 100.82,390.989 r90 top (schematic designator R3)
R3_I2C_Bridge_2 "1kR" "RES 0402/1005 RF" 521.872,300.439 r90 top (schematic designator R3)
R3_I2C_Bridge_3 "1kR" "RES 0402/1005 RF" 73.252,290.487 r90 top (schematic designator R3)
R4_I2C_Bridge "1kR" "RES 0402/1005 RF" 101.82,390.989 r90 top (schematic designator R4)
R4_I2C_Bridge_2 "1kR" "RES 0402/1005 RF" 520.196,300.363 r90 top (schematic designator R4)
R4_I2C_Bridge_3 "1kR" "RES 0402/1005 RF" 74.329,290.487 r90 top (schematic designator R4)
R5_I2C_Bridge "1kR" "RES 0402/1005 RF" 102.895,390.989 r90 top (schematic designator R5)
R5_I2C_Bridge_2 "1kR" "RES 0402/1005 RF" 518.202,300.253 r90 top (schematic designator R5)
R5_I2C_Bridge_3 "1kR" "RES 0402/1005 RF" 75.407,290.487 r90 top (schematic designator R5)
R6_I2C_Bridge "1kR" "RES 0402/1005 RF" 103.955,390.989 r90 top (schematic designator R6)
R6_I2C_Bridge_2 "1kR" "RES 0402/1005 RF" 516.742,300.223 r90 top (schematic designator R6)
R6_I2C_Bridge_3 "1kR" "RES 0402/1005 RF" 76.484,290.487 r90 top (schematic designator R6)
R7_I2C_Bridge "1kR" "RES 0402/1005 RF" 105.028,390.989 r90 top (schematic designator R7)
R7_I2C_Bridge_2 "1kR" "RES 0402/1005 RF" 515.065,300.096 r90 top (schematic designator R7)
R7_I2C_Bridge_3 "1kR" "RES 0402/1005 RF" 77.562,290.487 r90 top (schematic designator R7)
R8_I2C_Bridge "1kR" "RES 0402/1005 RF" 106.896,388.645 r0 top (schematic designator R8)
R8_I2C_Bridge_2 "1kR" "RES 0402/1005 RF" 513.147,299.601 r90 top (schematic designator R8)
R8_I2C_Bridge_3 "1kR" "RES 0402/1005 RF" 80.422,288.781 r0 top (schematic designator R8)
R9_I2C_Bridge "1kR" "RES 0402/1005 RF" 106.896,387.59 r0 top (schematic designator R9)
R9_I2C_Bridge_2 "1kR" "RES 0402/1005 RF" 531.816,298.788 r90 top (schematic designator R9)
R9_I2C_Bridge_3 "1kR" "RES 0402/1005 RF" 80.422,287.808 r0 top (schematic designator R9)
R10_I2C_Bridge "1kR" "RES 0402/1005 RF" 106.896,386.535 r0 top (schematic designator R10)
R10_I2C_Bridge_2 "1kR" "RES 0402/1005 RF" 524.764,285.123 r90 top (schematic designator R10)
R10_I2C_Bridge_3 "1kR" "RES 0402/1005 RF" 80.422,286.834 r0 top (schematic designator R10)
R11 "10kR" "RES 0402/1005 RF" 51.56,183.563 r180 top
R12 "95.3kR" "RES 0402/1005 RF" 45.844,173.839 r270 top
R13 "10kR" "RES 0402/1005 RF" 52.05,174.091 r180 top
R14 "0mR" "RES 0402/1005 RF" 192.113,173.126 r90 top
R15 "95.3kR" "RES 0402/1005 RF" 45.94,183.113 r270 top
R16 "0mR" "RES 0402/1005 RF" 196.177,172.872 r90 top
R17 "95.3kR" "RES 0402/1005 RF" 45.94,185.524 r90 top
R18 "24.9kR" "RES 0402/1005 RF" 51.56,184.471 r180 top
R19 "4.87kR" "RES 0402/1005 RF" 44.801,173.839 r90 top
R20 "95.3kR" "RES 0402/1005 RF" 45.822,176.136 r90 top
R21 "24.9kR" "RES 0402/1005 RF" 52.05,175.125 r180 top
R22 "0mR" "RES 0402/1005 RF" 192.367,170.84 r90 top
R23 "4.87kR" "RES 0402/1005 RF" 44.92,183.113 r90 top
R24 "0mR" "RES 0402/1005 RF" 196.05,170.84 r90 top
R25 "4.87kR" "RES 0402/1005 RF" 44.92,185.524 r270 top
R26 "4.87kR" "RES 0402/1005 RF" 44.801,176.136 r270 top
R27 "1.02kR" "RES 0402/1005 RF" 44.818,167.684 r0 top
R28 "1.02kR" "RES 0402/1005 RF" 43.129,179.425 r270 top
R29 "10kR" "RES 0402/1005 RF" 43.904,169.348 r90 top
R30 "10kR" "RES 0402/1005 RF" 44.831,180.9 r180 top
R31 "39.2R" "RES 0402/1005 RF" 174.855,345.25 r90 top
R32 "39.2R" "RES 0402/1005 RF" 170.02,345.25 r90 top
R33 "39.2R" "RES 0402/1005 RF" 158.287,340.144 r180 top
R34 "39.2R" "RES 0402/1005 RF" 158.287,339.055 r180 top
R35 "39.2R" "RES 0402/1005 RF" 173.646,345.25 r90 top
R36 "39.2R" "RES 0402/1005 RF" 167.603,345.25 r90 top
R37 "39.2R" "RES 0402/1005 RF" 158.287,337.967 r180 top
R38 "39.2R" "RES 0402/1005 RF" 162.769,345.25 r90 top
R39 "39.2R" "RES 0402/1005 RF" 171.229,345.25 r90 top
R40 "39.2R" "RES 0402/1005 RF" 166.395,345.25 r90 top
R41 "39.2R" "RES 0402/1005 RF" 158.287,341.233 r180 top
R42 "39.2R" "RES 0402/1005 RF" 172.438,345.25 r90 top
R43 "39.2R" "RES 0402/1005 RF" 178.481,345.25 r90 top
R44 "39.2R" "RES 0402/1005 RF" 163.977,345.25 r90 top
R45 "39.2R" "RES 0402/1005 RF" 158.287,343.411 r180 top
R46 "39.2R" "RES 0402/1005 RF" 158.287,333.611 r180 top
R47 "39.2R" "RES 0402/1005 RF" 177.272,345.25 r90 top
R48 "39.2R" "RES 0402/1005 RF" 158.287,342.322 r180 top
R49 "39.2R" "RES 0402/1005 RF" 168.812,345.25 r90 top
R50 "39.2R" "RES 0402/1005 RF" 176.063,345.25 r90 top
R51 "39.2R" "RES 0402/1005 RF" 158.287,335.789 r180 top
R52 "36R" "RES 0402/1005 RF" 158.287,331.433 r180 top
R53 "39.2R" "RES 0402/1005 RF" 158.287,344.5 r180 top
R54 "36R" "RES 0402/1005 RF" 158.287,332.522 r180 top
R55 "39.2R" "RES 0402/1005 RF" 165.186,345.25 r90 top
R56 "499R" "RES 0402/1005 RF" 162.91,338.184 r180 top
R57 "39.2R" "RES 0402/1005 RF" 158.287,336.878 r180 top
R58 "4.7kR" "RES 0402/1005 RF" 162.91,339.242 r180 top
R59 "39.2R" "RES 0402/1005 RF" 158.287,334.7 r180 top
R60 "1kR" "RES 0402/1005 RF" 184.994,348.704 r180 top
R61 "240R" "RES 0402/1005 RF" 198.031,345.611 r90 top
R62 "240R" "RES 0402/1005 RF" 186.195,345.262 r90 top
R63 "240R" "RES 0402/1005 RF" 156.464,323.541 r180 top
R64 "240R" "RES 0402/1005 RF" 181.458,347.789 r90 top
R65 "4.7kR" "RES 0402/1005 RF" 50.624,266.152 r180 top
R66 "4.7kR" "RES 0402/1005 RF" 50.624,267.233 r180 top
R67 "4.7kR" "RES 0402/1005 RF" 50.624,264.12 r180 top
R68 "4.7kR" "RES 0402/1005 RF" 50.624,265.136 r180 top
R69 "100R" "RES 0402/1005 RF" 46.317,322.097 r90 top
R70 "100R" "RES 0402/1005 RF" 52.159,322.097 r90 top
R71 "0R" "RES 0402/1005 RF" 47.333,270.662 r180 top
R72 "0R" "RES 0402/1005 RF" 47.333,269.646 r180 top
R73 "0R" "RES 0402/1005 RF" 49.495,270.662 r180 top
R74 "0R" "RES 0402/1005 RF" 49.495,269.646 r180 top
R75 "100R" "RES 0402/1005 RF" 90.504,259.536 r180 top
R76 "100R" "RES 0402/1005 RF" 110.431,258.992 r0 top
R77 "7.5kR" "RES 0402/1005 RF" 130.603,450.906 r180 top
R78 "100R" "RES 0402/1005 RF" 143.878,407.053 r0 top
R79 "100R" "RES 0402/1005 RF" 38.837,415.773 r0 top
R80 "100R" "RES 0402/1005 RF" 211.181,228.994 r0 top
R81 "100R" "RES 0402/1005 RF" 218.91,265.7 r180 top
R82 "100R" "RES 0402/1005 RF" 195.288,294.03 r90 top
R83 "4.7kR" "RES 0402/1005 RF" 108.547,344.313 r0 top
R84 "4.7kR" "RES 0402/1005 RF" 108.801,340.893 r0 top
R85 "4.7kR" "RES 0402/1005 RF" 108.547,343.433 r0 top
R86 "4.7kR" "RES 0402/1005 RF" 108.801,342.036 r0 top
R87 "30R" "RES 0402/1005 RF" 138.537,332.814 r180 bottom
R88 "30R" "RES 0402/1005 RF" 138.537,330.731 r180 bottom
R89 "30R" "RES 0402/1005 RF" 138.537,338.021 r180 bottom
R90 "30R" "RES 0402/1005 RF" 138.537,335.938 r180 bottom
R91 "0R" "RES 0402/1005 RF" 138.537,336.979 r180 bottom
R92 "0R" "RES 0402/1005 RF" 138.537,339.062 r180 bottom
R93 "0R" "RES 0402/1005 RF" 138.537,340.103 r180 bottom
R94 "0R" "RES 0402/1005 RF" 138.537,329.689 r180 bottom
R95 "30R" "RES 0402/1005 RF" 138.537,331.772 r180 bottom
R96 "30R" "RES 0402/1005 RF" 138.537,334.896 r180 bottom
R97 "4.7kR" "RES 0402/1005 RF" 138.537,333.855 r180 bottom
R98 "4.7kR" "RES 0402/1005 RF" 99.424,296.697 r180 bottom
R99 "4.7kR" "RES 0402/1005 RF" 367.411,60.089 r90 top
R100 "Resistance" "RES 0402/1005 RF" 318.491,435.623 r0 top
R101 "30R" "RES 0402/1005 RF" 133.566,322.351 r180 top
R102 "30R" "RES 0402/1005 RF" 133.566,320.319 r180 top
R103 "30R" "RES 0402/1005 RF" 133.566,318.287 r180 top
R104 "30R" "RES 0402/1005 RF" 133.566,316.255 r180 top
R105 "30R" "RES 0402/1005 RF" 133.566,321.335 r180 top
R106 "1kR" "RES 0402/1005 RF" 96.99,424.332 r180 top
R107 "30R" "RES 0402/1005 RF" 133.566,319.303 r180 top
R108 "30R" "RES 0402/1005 RF" 133.566,317.271 r180 top
R109 "1kR" "RES 0402/1005 RF" 142.964,455.193 r0 top
R110 "30R" "RES 0402/1005 RF" 133.566,323.367 r180 top
R111 "30R" "RES 0402/1005 RF" 133.566,315.214 r180 top
R112 "30R" "RES 0402/1005 RF" 133.566,314.223 r180 top
R113 "34.8kR" "RES 0402/1005 RF" 367.741,68.682 r90 top
R114 "10kR" "RES 0402/1005 RF" 360.883,68.682 r90 top
R115 "30R" "RES 0402/1005 RF" 98.895,322.478 r0 top
R116 "30R" "RES 0402/1005 RF" 96.101,322.478 r0 top
R117 "30R" "RES 0402/1005 RF" 91.783,322.478 r0 top
R118 "30R" "RES 0402/1005 RF" 87.465,322.478 r0 top
R119 "30R" "RES 0402/1005 RF" 98.641,324.256 r0 top
R120 "30R" "RES 0402/1005 RF" 94.323,324.256 r0 top
R121 "30R" "RES 0402/1005 RF" 90.005,324.256 r0 top
R122 "30R" "RES 0402/1005 RF" 86.83,323.875 r0 top
R123 "4.7kR" "RES 0402/1005 RF" 107.912,314.35 r0 top
R124 "1kR" "RES 0402/1005 RF" 173.063,241.833 r180 top
R125 "10kR" "RES 0402/1005 RF" 201.765,421.766 r180 top
R126 "100R" "RES 0402/1005 RF" 197.936,437.612 r270 top
R127 "0R" "RES 0402/1005 RF" 367.995,185.141 r90 top
R128 "10kR" "RES 0402/1005 RF" 179.645,415.882 r180 top
R129 "10kR" "RES 0402/1005 RF" 179.645,416.821 r180 top
R130 "0R" "RES 0402/1005 RF" 196.939,437.599 r270 top
R131 "0R" "RES 0402/1005 RF" 200.181,437.599 r270 top
R132 "0R" "RES 0402/1005 RF" 204.042,437.485 r90 top
R133 "0R" "RES 0402/1005 RF" 205.058,437.485 r90 top
R134 "0R" "RES 0402/1005 RF" 203.035,437.53 r90 top
R135 "4.7kR" "RES 0402/1005 RF" 47.725,278.917 r0 top
R136 "4.7kR" "RES 0402/1005 RF" 47.46,279.679 r0 top
R137 "4.7kR" "RES 0402/1005 RF" 47.275,284.886 r0 top
R138 "4.7kR" "RES 0402/1005 RF" 33.686,279.307 r0 top
R139 "0R" "RES 0402/1005 RF" 360.883,185.141 r90 top
R140 "2.2R" "RES 0402/1005 RF" 34.297,205.384 r180 top
R141 "0R" "RES 0402/1005 RF" 51.019,281.072 r0 top
R142 "0R" "RES 0402/1005 RF" 51.019,282.106 r0 top
R143 "0R" "RES 0402/1005 RF" 49.045,281.09 r0 top
R144 "0R" "RES 0402/1005 RF" 49.045,282.106 r0 top
R145 "4.7kR" "RES 0402/1005 RF" 47.206,289.077 r0 top
R146 "4.7kR" "RES 0402/1005 RF" 47.206,287.172 r0 top
R147 "4.7kR" "RES 0402/1005 RF" 47.206,288.061 r0 top
R148 "4.7kR" "RES 0402/1005 RF" 33.686,281.593 r0 top
R149 "196kR" "RES 0402/1005 RF" 34.323,204.343 r0 top
R150 "22k" "RES 0402/1005 RF" 42.652,206.468 r0 top
R151 "0R" "RES 0402/1005 RF" 51.863,297.915 r0 top
R152 "0R" "RES 0402/1005 RF" 51.816,296.899 r0 top
R153 "0R" "RES 0402/1005 RF" 49.45,297.915 r0 top
R154 "0R" "RES 0402/1005 RF" 49.45,296.899 r0 top
R155 "4.7kR" "RES 0402/1005 RF" 40.163,282.727 r0 top
R156 "4.7kR" "RES 0402/1005 RF" 40.163,281.711 r0 top
R157 "4.7kR" "RES 0402/1005 RF" 40.154,280.441 r0 top
R158 "4.7kR" "RES 0402/1005 RF" 33.686,280.568 r0 top
R159 "10kR" "RES 0402/1005 RF" 34.323,203.149 r0 top
R160 "910R" "RES 0402/1005 RF" 42.528,203.203 r180 top
R161 "0R" "RES 0402/1005 RF" 50.943,312.266 r0 top
R162 "0R" "RES 0402/1005 RF" 50.943,311.25 r0 top
R163 "0R" "RES 0402/1005 RF" 48.704,312.266 r0 top
R164 "0R" "RES 0402/1005 RF" 48.704,311.25 r0 top
R165 "100R" "RES 0402/1005 RF" 182.99,356.502 r0 top
R166 "100R" "RES 0402/1005 RF" 180.646,355.74 r0 top
R167 "100R" "RES 0402/1005 RF" 182.281,358.296 r90 top
R168 "100R" "RES 0402/1005 RF" 180.122,358.296 r90 top
R169 "100R" "RES 0402/1005 RF" 150.965,357.234 r0 top
R170 "100R" "RES 0402/1005 RF" 147.155,356.218 r0 top
R171 "100R" "RES 0402/1005 RF" 154.762,356.218 r0 top
R172 "100R" "RES 0402/1005 RF" 143.218,355.583 r0 top
R173 "500R" "RES 0402/1005 RF" 360.883,208.826 r90 top
R174 "0mR" "RES 0402/1005 RF" 167.244,539.921 r270 top
R175 "0mR" "RES 0402/1005 RF" 166.228,539.921 r270 top
R176 "0mR" "RES 0402/1005 RF" 165.212,539.921 r270 top
R177 "0mR" "RES 0402/1005 RF" 164.196,539.921 r270 top
R178 "0mR" "RES 0402/1005 RF" 167.244,542.334 r90 top
R179 "0mR" "RES 0402/1005 RF" 166.228,542.334 r90 top
R180 "0mR" "RES 0402/1005 RF" 165.212,542.334 r90 top
R181 "0mR" "RES 0402/1005 RF" 164.196,542.334 r90 top
R182 "1.02kR" "RES 0402/1005 RF" 178.585,543.303 r90 top
R183 "0mR" "RES 0402/1005 RF" 227.844,556.412 r90 top
R184 "0mR" "RES 0402/1005 RF" 228.733,556.412 r90 top
R185 "0mR" "RES 0402/1005 RF" 229.622,556.412 r90 top
R186 "0mR" "RES 0402/1005 RF" 230.511,556.412 r90 top
R187 "0mR" "RES 0402/1005 RF" 227.844,554.253 r270 top
R188 "0mR" "RES 0402/1005 RF" 228.733,554.253 r270 top
R189 "0mR" "RES 0402/1005 RF" 229.622,554.253 r270 top
R190 "0mR" "RES 0402/1005 RF" 230.511,554.253 r270 top
R191 "1.02kR" "RES 0402/1005 RF" 224.687,552.243 r0 top
R192 "0mR" "RES 0402/1005 RF" 6.377,209.702 r270 top
R193 "0mR" "RES 0402/1005 RF" 5.318,209.702 r270 top
R194 "0mR" "RES 0402/1005 RF" 4.26,209.702 r270 top
R195 "0mR" "RES 0402/1005 RF" 3.202,209.702 r270 top
R196 "0mR" "RES 0402/1005 RF" 6.377,211.734 r90 top
R197 "0mR" "RES 0402/1005 RF" 5.318,211.734 r90 top
R198 "0mR" "RES 0402/1005 RF" 4.26,211.734 r90 top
